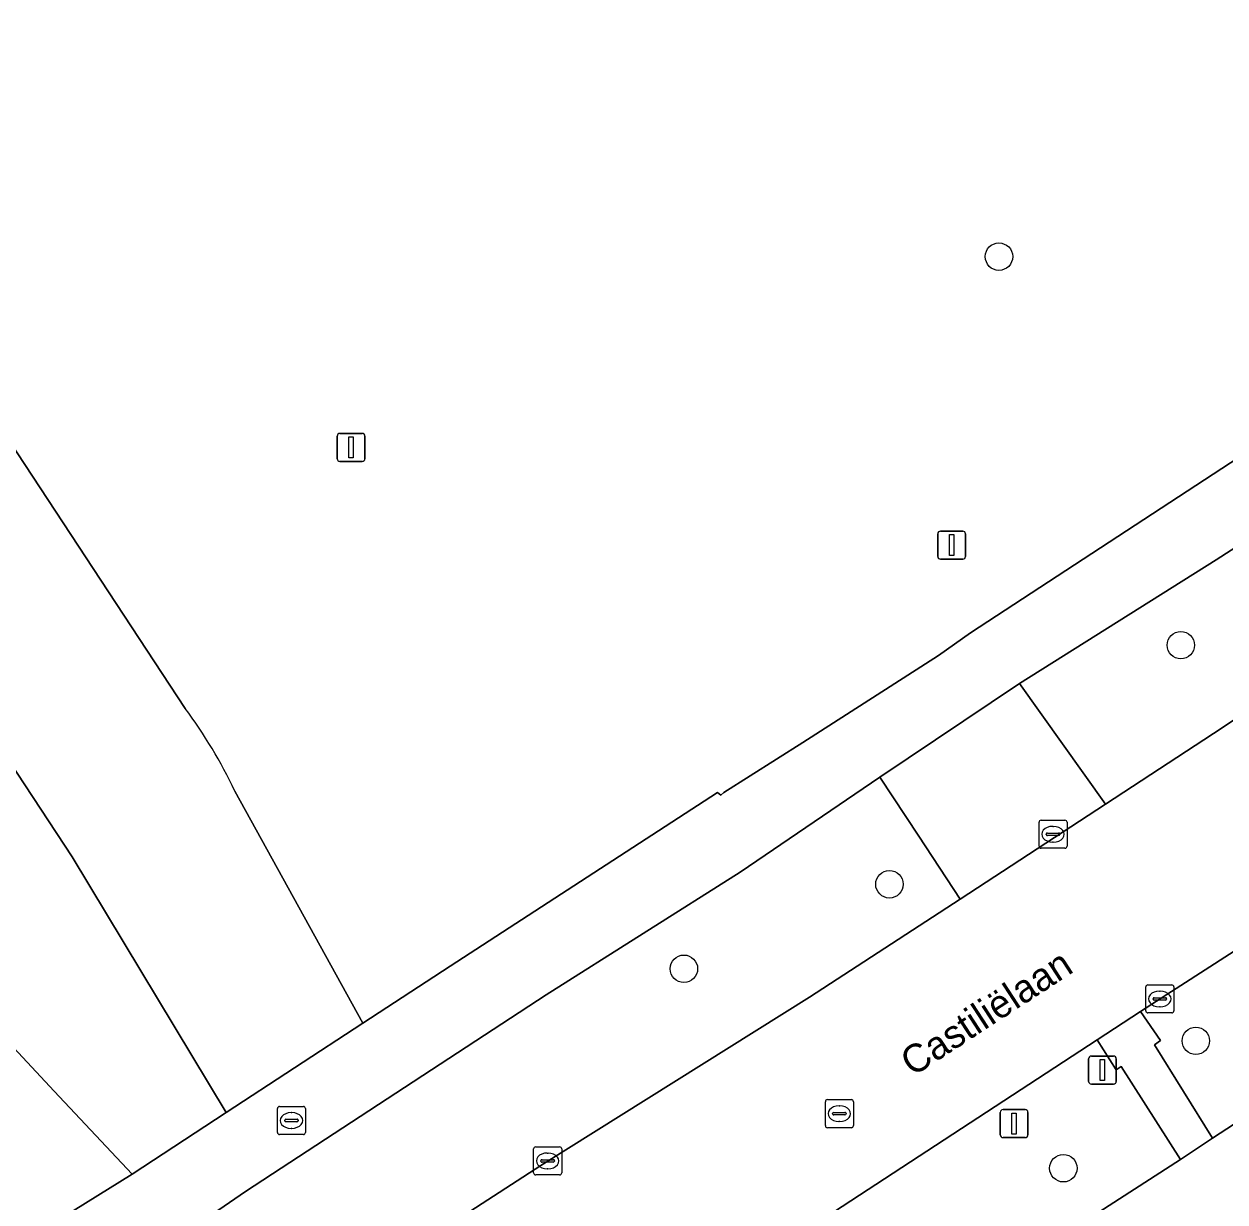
# Model space of a CAD drawing. Extents: x 159451 to 160664, y 388402 to 389723.
# Drawn here: x 159684.06 to 159726.89, y 389157.64 to 389199.64 of the extents above; entities that cross this region are included whole.
import ezdxf

# ---------------------------------------------------------------- set-up
doc = ezdxf.new("R2010")
doc.units = 0
for name, color, linetype in [('IMGEO_Berm_groen', 7, 'Continuous'), ('IMGEO_Boom', 7, 'Continuous'), ('IMGEO_Bouwland', 7, 'Continuous'), ('IMGEO_Fietspad_gesloten', 7, 'Continuous'), ('IMGEO_Groenvoorziening', 7, 'Continuous'), ('IMGEO_Kolk', 7, 'Continuous'), ('IMGEO_Lichtmast', 7, 'Continuous'), ('IMGEO_Openbare_ruimte_label', 7, 'Continuous'), ('IMGEO_Rijbaan_lokaal_gesloten', 7, 'Continuous'), ('IMGEO_Rijbaan_lokaal_open', 7, 'Continuous'), ('IMGEO_Rioolput', 7, 'Continuous'), ('IMGEO_Verkeersbordpaal', 7, 'Continuous'), ('IMGEO_Voetpad_open', 7, 'Continuous')]:
    doc.layers.add(name, color=color, linetype=linetype)

msp = doc.modelspace()

# ---------------------------------------------------------------- linework, layer by layer
at = {"layer": 'IMGEO_Berm_groen'}
for points in [[(159791.87, 389203.184), (159789.616, 389206.936), (159771.403, 389195.071), (159744.513, 389177.711), (159734.489, 389171.264), (159724.275, 389164.695), (159723.871, 389164.431), (159724.588, 389163.392), (159724.374, 389163.237), (159726.442, 389159.917), (159737.666, 389167.226), (159753.709, 389177.779), (159791.193, 389202.242)], [(159715.829, 389153.048), (159725.301, 389159.156), (159723.188, 389162.468), (159723.009, 389162.351), (159722.322, 389163.419), (159706.263, 389152.922), (159697.619, 389147.345), (159690.091, 389142.488), (159689.666, 389142.214), (159688.725, 389141.682), (159688.23, 389141.242)]]:
    msp.add_lwpolyline(points, dxfattribs=at)
msp.add_lwpolyline([(159732.761, 389178.498), (159733.084, 389182.02), (159731.823, 389183.917), (159726.565, 389180.529), (159719.558, 389176.127), (159722.626, 389171.817), (159726.781, 389174.542), (159730.042, 389176.743)], close=True, dxfattribs=at)
at = {"layer": 'IMGEO_Boom'}
for centre in [(159718.826, 389191.343), (159725.311, 389177.491), (159714.918, 389168.964), (159707.591, 389165.954), (159725.845, 389163.382), (159721.121, 389158.839)]:
    msp.add_circle(centre, 0.489, dxfattribs=at)
at = {"layer": 'IMGEO_Bouwland'}
msp.add_lwpolyline([(159679.04, 389168.125), (159685.128, 389161.585), (159687.914, 389158.632), (159691.273, 389160.827), (159685.775, 389169.94), (159657.638, 389212.73)], dxfattribs=at)
at = {"layer": 'IMGEO_Fietspad_gesloten'}
for points in [[(159683.696, 389152.464), (159687.097, 389154.672), (159691.96, 389158.015), (159702.684, 389165.018), (159709.597, 389169.401), (159714.574, 389172.778), (159719.558, 389176.127), (159726.565, 389180.529), (159731.823, 389183.917), (159737.096, 389187.355), (159758.299, 389200.996), (159781.643, 389216.263), (159789.265, 389221.193), (159827.078, 389245.82), (159832.314, 389249.122), (159833.66, 389250), (159874.622, 389276.708)], [(159858.151, 389269.353), (159792.67, 389226.891), (159787.277, 389223.364), (159784.328, 389221.435), (159717.814, 389177.926), (159716.666, 389177.127), (159711.829, 389174.024), (159709.019, 389172.233), (159708.905, 389172.147), (159708.794, 389172.235), (159699.251, 389166.039), (159696.145, 389164.01), (159691.273, 389160.827), (159687.914, 389158.632), (159677.234, 389152.002)], [(159886.805, 389257.668), (159883.73, 389262.298), (159864.845, 389250), (159823.884, 389223.328), (159798.419, 389206.786), (159791.193, 389202.242), (159753.709, 389177.779), (159737.666, 389167.226), (159726.442, 389159.917), (159725.301, 389159.156), (159715.829, 389153.048), (159696.672, 389140.641), (159692.451, 389138.046), (159686.936, 389134.846)]]:
    msp.add_lwpolyline(points, dxfattribs=at)
at = {"layer": 'IMGEO_Groenvoorziening'}
for points in [[(159691.581, 389172.29), (159696.145, 389164.01), (159699.251, 389166.039), (159708.794, 389172.235), (159708.905, 389172.147), (159709.019, 389172.233), (159711.829, 389174.024), (159716.666, 389177.127), (159717.814, 389177.926), (159784.328, 389221.435), (159782.969, 389223.526), (159785.892, 389225.495), (159787.277, 389223.364), (159792.67, 389226.891), (159858.151, 389269.353)], [(159653.827, 389229.979), (159689.805, 389175.234)], [(159702.485, 389158.94), (159712.067, 389164.934), (159717.44, 389168.436), (159715.973, 389170.679), (159714.574, 389172.778), (159709.597, 389169.401), (159702.684, 389165.018), (159691.96, 389158.015), (159687.097, 389154.672), (159683.696, 389152.464), (159677.543, 389148.933)], [(159677.234, 389152.002), (159687.914, 389158.632), (159685.128, 389161.585), (159679.04, 389168.125)], [(159676.524, 389144.37), (159677.26, 389142.765), (159686.462, 389148.273), (159693.85, 389153.343), (159702.485, 389158.94)]]:
    msp.add_lwpolyline(points, dxfattribs=at)
msp.add_arc((159675.104, 389164.358), 18.287, 25.7068, 36.495, dxfattribs=at)
at = {"layer": 'IMGEO_Kolk'}
for p, q in [((159720.253, 389170.323), (159720.253, 389171.175)), ((159720.328, 389171.249), (159721.18, 389171.249)), ((159720.741, 389171.029), (159720.766, 389171.029)), ((159721.254, 389171.175), (159721.254, 389170.323)), ((159720.512, 389170.743), (159720.512, 389170.755)), ((159720.95, 389170.706), (159720.552, 389170.706)), ((159720.555, 389170.792), (159720.953, 389170.792)), ((159720.996, 389170.755), (159720.996, 389170.743)), ((159721.18, 389170.249), (159720.328, 389170.249)), ((159720.764, 389170.469), (159720.739, 389170.469)), ((159724.061, 389164.451), (159724.061, 389165.303)), ((159724.136, 389165.377), (159724.988, 389165.377)), ((159724.549, 389165.157), (159724.574, 389165.157)), ((159725.062, 389165.303), (159725.062, 389164.451)), ((159724.32, 389164.871), (159724.32, 389164.883)), ((159724.758, 389164.834), (159724.36, 389164.834)), ((159724.363, 389164.92), (159724.761, 389164.92)), ((159724.572, 389164.597), (159724.547, 389164.597)), ((159724.804, 389164.883), (159724.804, 389164.871)), ((159724.988, 389164.377), (159724.136, 389164.377)), ((159702.231, 389158.675), (159702.231, 389159.527)), ((159702.306, 389159.601), (159703.158, 389159.601)), ((159703.232, 389159.527), (159703.232, 389158.675)), ((159702.49, 389159.095), (159702.49, 389159.107)), ((159702.928, 389159.058), (159702.53, 389159.058)), ((159702.533, 389159.144), (159702.931, 389159.144)), ((159702.719, 389159.381), (159702.744, 389159.381)), ((159702.974, 389159.107), (159702.974, 389159.095)), ((159703.158, 389158.601), (159702.306, 389158.601)), ((159702.742, 389158.821), (159702.717, 389158.821))]:
    msp.add_line(p, q, dxfattribs=at)
for points in [[(159720.253, 389170.323), (159720.253, 389171.175)], [(159720.328, 389171.249), (159721.18, 389171.249)], [(159721.254, 389171.175), (159721.254, 389170.323)], [(159721.18, 389170.249), (159720.328, 389170.249)], [(159724.061, 389164.451), (159724.061, 389165.303)], [(159724.136, 389165.377), (159724.988, 389165.377)], [(159725.062, 389165.303), (159725.062, 389164.451)], [(159724.988, 389164.377), (159724.136, 389164.377)], [(159702.231, 389158.675), (159702.231, 389159.527)], [(159702.306, 389159.601), (159703.158, 389159.601)], [(159703.232, 389159.527), (159703.232, 389158.675)], [(159703.158, 389158.601), (159702.306, 389158.601)]]:
    msp.add_lwpolyline(points, dxfattribs=at)
for centre, radius, start, end in [((159720.33, 389171.173), 0.0765, 91.552, 178.448), ((159720.33, 389171.173), 0.0765, 91.552, 178.448), ((159721.178, 389171.173), 0.0765, 1.552, 88.448), ((159721.178, 389171.173), 0.0765, 1.552, 88.448), ((159720.552, 389170.752), 0.0403, 85.8775, 175.7526), ((159720.549, 389170.742), 0.0366, 178.938, 274.7102), ((159720.953, 389170.749), 0.043, 264.8664, 352.4533), ((159720.957, 389170.754), 0.0386, 1.7309, 96.639), ((159720.33, 389170.325), 0.0765, 181.552, 268.448), ((159720.33, 389170.325), 0.0765, 181.552, 268.448), ((159721.178, 389170.325), 0.0765, 271.552, 358.448), ((159721.178, 389170.325), 0.0765, 271.552, 358.448), ((159724.138, 389165.301), 0.0765, 91.552, 178.448), ((159724.138, 389165.301), 0.0765, 91.552, 178.448), ((159724.986, 389165.301), 0.0765, 1.552, 88.448), ((159724.986, 389165.301), 0.0765, 1.552, 88.448), ((159724.36, 389164.88), 0.0403, 85.8775, 175.7526), ((159724.357, 389164.87), 0.0366, 178.938, 274.7102), ((159724.761, 389164.877), 0.043, 264.8664, 352.4533), ((159724.765, 389164.882), 0.0386, 1.7309, 96.639), ((159724.138, 389164.453), 0.0765, 181.552, 268.448), ((159724.138, 389164.453), 0.0765, 181.552, 268.448), ((159724.986, 389164.453), 0.0765, 271.552, 358.448), ((159724.986, 389164.453), 0.0765, 271.552, 358.448), ((159702.308, 389159.525), 0.0765, 91.552, 178.448), ((159702.308, 389159.525), 0.0765, 91.552, 178.448), ((159703.156, 389159.525), 0.0765, 1.552, 88.448), ((159703.156, 389159.525), 0.0765, 1.552, 88.448), ((159702.53, 389159.104), 0.0403, 85.8775, 175.7526), ((159702.527, 389159.094), 0.0366, 178.938, 274.7102), ((159702.931, 389159.101), 0.043, 264.8664, 352.4533), ((159702.935, 389159.106), 0.0386, 1.7309, 96.639), ((159702.308, 389158.677), 0.0765, 181.552, 268.448), ((159702.308, 389158.677), 0.0765, 181.552, 268.448), ((159703.156, 389158.677), 0.0765, 271.552, 358.448), ((159703.156, 389158.677), 0.0765, 271.552, 358.448)]:
    msp.add_arc(centre, radius, start, end, dxfattribs=at)
for centre, major_axis, ratio, start_param, end_param in [((159720.74, 389170.749), (-0.387, 0.002), 0.722429, 4.712389, 7.853982), ((159720.765, 389170.749), (-0.39, 0.002), 0.717154, 1.570796, 4.712389), ((159724.548, 389164.877), (-0.387, 0.002), 0.722429, 4.712389, 7.853982), ((159724.573, 389164.877), (-0.39, 0.002), 0.717154, 1.570796, 4.712389), ((159702.718, 389159.101), (-0.387, 0.002), 0.722429, 4.712389, 7.853982), ((159702.743, 389159.101), (-0.39, 0.002), 0.717154, 1.570796, 4.712389)]:
    msp.add_ellipse(centre, major_axis=major_axis, ratio=ratio, start_param=start_param, end_param=end_param, dxfattribs=at)
at = {"layer": 'IMGEO_Lichtmast'}
for p, q in [((159695.225, 389184.14), (159695.225, 389184.94)), ((159695.225, 389184.94), (159695.225, 389184.14)), ((159695.325, 389185.04), (159696.115, 389185.04)), ((159696.115, 389185.04), (159695.325, 389185.04)), ((159696.215, 389184.94), (159696.215, 389184.14)), ((159696.215, 389184.14), (159696.215, 389184.94)), ((159696.115, 389184.04), (159695.325, 389184.04)), ((159695.325, 389184.04), (159696.115, 389184.04)), ((159722.12, 389162.838), (159722.91, 389162.838)), ((159722.91, 389162.838), (159722.12, 389162.838)), ((159722.02, 389161.938), (159722.02, 389162.738)), ((159722.02, 389162.738), (159722.02, 389161.938)), ((159723.01, 389162.738), (159723.01, 389161.938)), ((159723.01, 389161.938), (159723.01, 389162.738)), ((159722.91, 389161.838), (159722.12, 389161.838)), ((159722.12, 389161.838), (159722.91, 389161.838))]:
    msp.add_line(p, q, dxfattribs=at)
for points in [[(159695.645, 389184.915), (159695.795, 389184.915), (159695.795, 389184.165), (159695.645, 389184.165), (159695.645, 389184.915)], [(159722.44, 389162.713), (159722.59, 389162.713), (159722.59, 389161.963), (159722.44, 389161.963), (159722.44, 389162.713)]]:
    msp.add_lwpolyline(points, dxfattribs=at)
for centre, start, end in [((159695.325, 389184.94), 90, 180), ((159695.325, 389184.94), 90, 180), ((159696.115, 389184.94), 0, 90), ((159696.115, 389184.94), 360, 90), ((159695.325, 389184.14), 180, 270), ((159695.325, 389184.14), 180, 270), ((159696.115, 389184.14), 270, 0), ((159696.115, 389184.14), 270, 0), ((159722.12, 389162.738), 90, 180), ((159722.12, 389162.738), 90, 180), ((159722.91, 389162.738), 0, 90), ((159722.91, 389162.738), 360, 90), ((159722.12, 389161.938), 180, 270), ((159722.12, 389161.938), 180, 270), ((159722.91, 389161.938), 270, 0), ((159722.91, 389161.938), 270, 0)]:
    msp.add_arc(centre, 0.1, start, end, dxfattribs=at)
at = {"layer": 'IMGEO_Rijbaan_lokaal_gesloten'}
for points in [[(159689.805, 389175.234), (159653.827, 389229.979)], [(159647.183, 389229.023), (159648.051, 389227.67), (159656.489, 389214.521), (159657.638, 389212.73), (159685.775, 389169.94), (159691.273, 389160.827), (159696.145, 389164.01), (159691.581, 389172.29)], [(159786.052, 389212.871), (159754.281, 389192.419), (159741.003, 389183.824), (159737.877, 389181.8), (159732.761, 389178.498), (159730.042, 389176.743), (159726.781, 389174.542), (159722.626, 389171.817), (159717.44, 389168.436), (159712.067, 389164.934), (159702.485, 389158.94), (159693.85, 389153.343), (159697.619, 389147.345), (159706.263, 389152.922), (159722.322, 389163.419), (159723.871, 389164.431), (159724.275, 389164.695), (159734.489, 389171.264), (159744.513, 389177.711), (159771.403, 389195.071), (159789.616, 389206.936)]]:
    msp.add_lwpolyline(points, dxfattribs=at)
msp.add_arc((159675.104, 389164.358), 18.287, 25.7068, 36.495, dxfattribs=at)
at = {"layer": 'IMGEO_Rijbaan_lokaal_open'}
msp.add_lwpolyline([(159722.626, 389171.817), (159719.558, 389176.127), (159714.574, 389172.778), (159715.973, 389170.679), (159717.44, 389168.436)], close=True, dxfattribs=at)
at = {"layer": 'IMGEO_Rioolput'}
for p, q in [((159712.634, 389160.359), (159712.634, 389161.211)), ((159712.709, 389161.285), (159713.561, 389161.285)), ((159713.635, 389161.211), (159713.635, 389160.359)), ((159693.095, 389160.116), (159693.095, 389160.968)), ((159693.17, 389161.042), (159694.022, 389161.042)), ((159693.583, 389160.822), (159693.608, 389160.822)), ((159694.096, 389160.968), (159694.096, 389160.116)), ((159712.893, 389160.779), (159712.893, 389160.791)), ((159713.331, 389160.742), (159712.933, 389160.742)), ((159712.936, 389160.828), (159713.334, 389160.828)), ((159713.122, 389161.065), (159713.147, 389161.065)), ((159713.377, 389160.791), (159713.377, 389160.779)), ((159693.354, 389160.536), (159693.354, 389160.548)), ((159693.792, 389160.499), (159693.394, 389160.499)), ((159693.397, 389160.585), (159693.795, 389160.585)), ((159693.838, 389160.548), (159693.838, 389160.536)), ((159713.561, 389160.285), (159712.709, 389160.285)), ((159713.145, 389160.505), (159713.12, 389160.505)), ((159694.022, 389160.042), (159693.17, 389160.042)), ((159693.606, 389160.262), (159693.581, 389160.262))]:
    msp.add_line(p, q, dxfattribs=at)
for points in [[(159712.634, 389160.359), (159712.634, 389161.211)], [(159712.709, 389161.285), (159713.561, 389161.285)], [(159713.635, 389161.211), (159713.635, 389160.359)], [(159693.095, 389160.116), (159693.095, 389160.968)], [(159693.17, 389161.042), (159694.022, 389161.042)], [(159694.096, 389160.968), (159694.096, 389160.116)], [(159713.561, 389160.285), (159712.709, 389160.285)], [(159694.022, 389160.042), (159693.17, 389160.042)]]:
    msp.add_lwpolyline(points, dxfattribs=at)
for centre, radius, start, end in [((159712.711, 389161.209), 0.0765, 91.552, 178.448), ((159712.711, 389161.209), 0.0765, 91.552, 178.448), ((159713.559, 389161.209), 0.0765, 1.552, 88.448), ((159713.559, 389161.209), 0.0765, 1.552, 88.448), ((159693.172, 389160.966), 0.0765, 91.552, 178.448), ((159693.172, 389160.966), 0.0765, 91.552, 178.448), ((159694.02, 389160.966), 0.0765, 1.552, 88.448), ((159694.02, 389160.966), 0.0765, 1.552, 88.448), ((159712.933, 389160.788), 0.0403, 85.8775, 175.7526), ((159712.93, 389160.778), 0.0366, 178.938, 274.7102), ((159713.334, 389160.785), 0.043, 264.8664, 352.4533), ((159713.338, 389160.79), 0.0386, 1.7309, 96.639), ((159693.394, 389160.545), 0.0403, 85.8775, 175.7526), ((159693.391, 389160.535), 0.0366, 178.938, 274.7102), ((159693.795, 389160.542), 0.043, 264.8664, 352.4533), ((159693.799, 389160.547), 0.0386, 1.7309, 96.639), ((159712.711, 389160.361), 0.0765, 181.552, 268.448), ((159712.711, 389160.361), 0.0765, 181.552, 268.448), ((159713.559, 389160.361), 0.0765, 271.552, 358.448), ((159713.559, 389160.361), 0.0765, 271.552, 358.448), ((159693.172, 389160.118), 0.0765, 181.552, 268.448), ((159693.172, 389160.118), 0.0765, 181.552, 268.448), ((159694.02, 389160.118), 0.0765, 271.552, 358.448), ((159694.02, 389160.118), 0.0765, 271.552, 358.448)]:
    msp.add_arc(centre, radius, start, end, dxfattribs=at)
for centre, major_axis, ratio, start_param, end_param in [((159693.582, 389160.542), (-0.387, 0.002), 0.722429, 4.712389, 7.853982), ((159693.607, 389160.542), (-0.39, 0.002), 0.717154, 1.570796, 4.712389), ((159713.121, 389160.785), (-0.387, 0.002), 0.722429, 4.712389, 7.853982), ((159713.146, 389160.785), (-0.39, 0.002), 0.717154, 1.570796, 4.712389)]:
    msp.add_ellipse(centre, major_axis=major_axis, ratio=ratio, start_param=start_param, end_param=end_param, dxfattribs=at)
at = {"layer": 'IMGEO_Verkeersbordpaal'}
for p, q in [((159716.642, 389180.657), (159716.642, 389181.457)), ((159716.642, 389181.457), (159716.642, 389180.657)), ((159716.742, 389181.557), (159717.532, 389181.557)), ((159717.532, 389181.557), (159716.742, 389181.557)), ((159717.632, 389181.457), (159717.632, 389180.657)), ((159717.632, 389180.657), (159717.632, 389181.457)), ((159717.532, 389180.557), (159716.742, 389180.557)), ((159716.742, 389180.557), (159717.532, 389180.557)), ((159718.87, 389160.032), (159718.87, 389160.832)), ((159718.87, 389160.832), (159718.87, 389160.032)), ((159718.97, 389160.932), (159719.76, 389160.932)), ((159719.76, 389160.932), (159718.97, 389160.932)), ((159719.86, 389160.832), (159719.86, 389160.032)), ((159719.86, 389160.032), (159719.86, 389160.832)), ((159719.76, 389159.932), (159718.97, 389159.932)), ((159718.97, 389159.932), (159719.76, 389159.932))]:
    msp.add_line(p, q, dxfattribs=at)
for points in [[(159717.062, 389181.432), (159717.212, 389181.432), (159717.212, 389180.682), (159717.062, 389180.682), (159717.062, 389181.432)], [(159719.29, 389160.807), (159719.44, 389160.807), (159719.44, 389160.057), (159719.29, 389160.057), (159719.29, 389160.807)]]:
    msp.add_lwpolyline(points, dxfattribs=at)
for centre, start, end in [((159716.742, 389181.457), 90, 180), ((159716.742, 389181.457), 90, 180), ((159717.532, 389181.457), 0, 90), ((159717.532, 389181.457), 360, 90), ((159716.742, 389180.657), 180, 270), ((159716.742, 389180.657), 180, 270), ((159717.532, 389180.657), 270, 0), ((159717.532, 389180.657), 270, 0), ((159718.97, 389160.832), 90, 180), ((159718.97, 389160.832), 90, 180), ((159719.76, 389160.832), 0, 90), ((159719.76, 389160.832), 360, 90), ((159718.97, 389160.032), 180, 270), ((159718.97, 389160.032), 180, 270), ((159719.76, 389160.032), 270, 0), ((159719.76, 389160.032), 270, 0)]:
    msp.add_arc(centre, 0.1, start, end, dxfattribs=at)
at = {"layer": 'IMGEO_Voetpad_open'}
msp.add_lwpolyline([(159724.374, 389163.237), (159724.588, 389163.392), (159723.871, 389164.431), (159722.322, 389163.419), (159723.009, 389162.351), (159723.188, 389162.468), (159725.301, 389159.156), (159726.442, 389159.917)], close=True, dxfattribs=at)

# ---------------------------------------------------------------- texts
at = {"layer": 'IMGEO_Openbare_ruimte_label'}
msp.add_text('Castiliëlaan', height=1, rotation=33.0863, dxfattribs=at).set_placement((159715.746, 389162.088))

doc.saveas('drawing.dxf')
